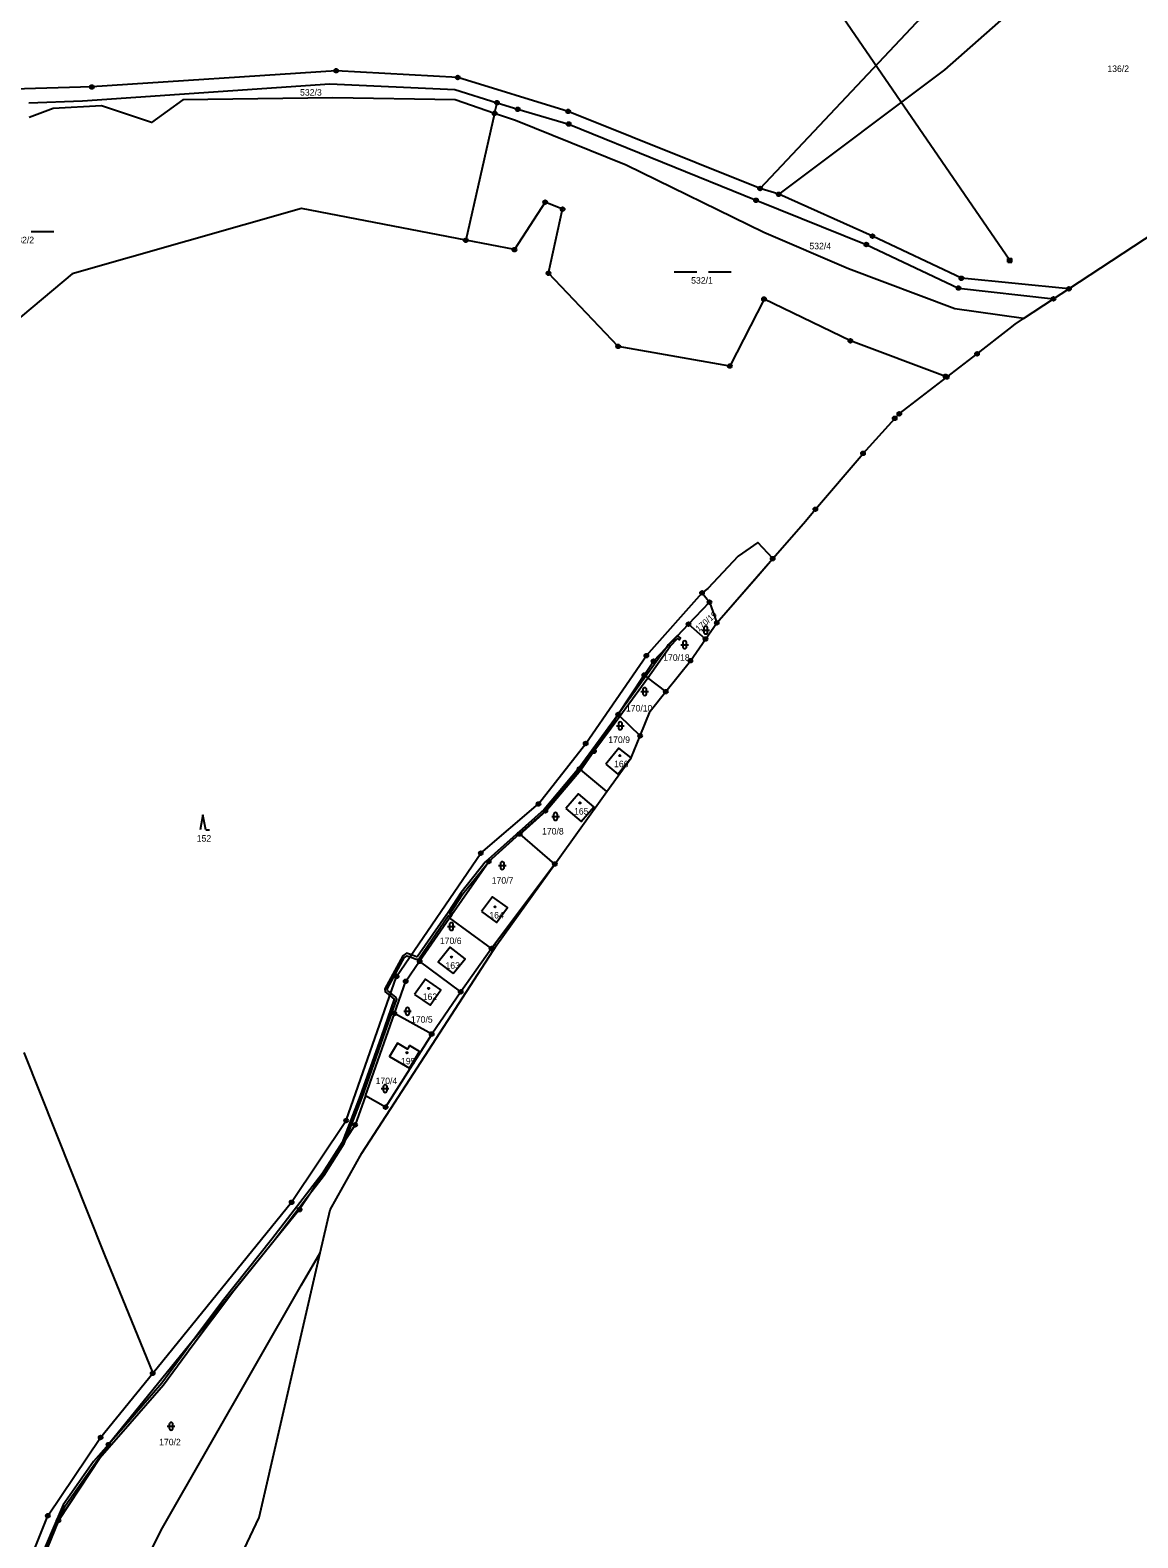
# Model space of a CAD drawing. Extents: x -758582 to -751794, y -998770 to -994350.
# Drawn here: x -755930.2 to -755639.5, y -996868.5 to -996472.9 of the extents above; entities that cross this region are included whole.
import ezdxf

# ---------------------------------------------------------------- set-up
doc = ezdxf.new("R2010")
doc.units = 0
for name, color, linetype in [('Hranice parcel', 7, 'Continuous'), ('Parcelní čísla', 7, 'Continuous'), ('Poz předměty', 7, 'Continuous'), ('Věcná břemena k části', 7, 'Continuous'), ('Značky bodu BP', 7, 'Continuous'), ('Značky budov', 7, 'Continuous'), ('Značky kultur', 7, 'Continuous')]:
    doc.layers.add(name, color=color, linetype=linetype)

msp = doc.modelspace()

# ---------------------------------------------------------------- linework, layer by layer
at = {"layer": 'Hranice parcel'}
for p, q in [((-755808.28, -996494.77), (-755807.65, -996491.97)), ((-755808.28, -996494.77), (-755815.82, -996528.07)), ((-755733.73, -996515.99), (-755738.63, -996514.47)), ((-755657.57, -996540.79), (-755632.12, -996524.1)), ((-755669.5, -996548.61), (-755661.64, -996543.45)), ((-755661.64, -996543.45), (-755657.57, -996540.79)), ((-755689.6, -996563.96), (-755681.68, -996557.85)), ((-755757.39, -996628.81), (-755751.89, -996623.03)), ((-755751.89, -996623.03), (-755749.99, -996628.46)), ((-755752.94, -996632.69), (-755757.39, -996628.81)), ((-755752.94, -996632.69), (-755749.99, -996628.46)), ((-755775.86, -996652.51), (-755769.01, -996642.14)), ((-755772.48, -996663.86), (-755770.1, -996658.08)), ((-755778.8, -996672.66), (-755772.48, -996663.86)), ((-755792.5, -996691.74), (-755778.8, -996672.66)), ((-755792.5, -996691.74), (-755809.1, -996713.88)), ((-755827.96, -996717.24), (-755820.08, -996705.87)), ((-755809.1, -996713.88), (-755820.08, -996705.87)), ((-755817.17, -996725.28), (-755827.96, -996717.24)), ((-755809.1, -996713.88), (-755817.17, -996725.28)), ((-755817.17, -996725.28), (-755824.8, -996736.35)), ((-755842.13, -996752.56), (-755834.58, -996730.95)), ((-755824.8, -996736.35), (-755834.58, -996730.95))]:
    msp.add_line(p, q, dxfattribs=at)
for points in [[(-755738.63, -996514.47), (-755697.58, -996470.89), (-755661.47, -996437.55), (-755587.13, -996400.84)], [(-755578.05, -996410.74), (-755604.07, -996420.95), (-755651.18, -996448.91), (-755690.24, -996483.38), (-755733.73, -996515.99)], [(-755738.63, -996514.47), (-755788.99, -996494.25), (-755817.97, -996485.34), (-755849.85, -996483.58), (-755913.99, -996487.85), (-755981.92, -996489.8), (-756037.02, -996471.24)], [(-755930.55, -996492.03), (-755916.39, -996491.48), (-755851.5, -996487.03), (-755818.69, -996488.48), (-755807.65, -996491.97)], [(-755808.28, -996494.77), (-755818.67, -996491.26), (-755850.72, -996490.71), (-755890.14, -996491.25), (-755898.35, -996497.16), (-755911.43, -996492.83), (-755924.16, -996493.48), (-755930.4, -996495.89)], [(-755807.65, -996491.97), (-755802.23, -996493.69), (-755788.84, -996497.56), (-755739.69, -996517.57), (-755710.74, -996529.16), (-755686.54, -996540.6), (-755661.64, -996543.45)], [(-755669.5, -996548.61), (-755687.54, -996546.02), (-755715.4, -996535.58), (-755737.6, -996526.05), (-755773.75, -996508.36), (-755802.77, -996496.64), (-755808.28, -996494.77)], [(-755657.57, -996540.79), (-755685.81, -996538.04), (-755709.11, -996527), (-755733.73, -996515.99)], [(-755815.82, -996528.07), (-755858.93, -996519.76), (-755919.17, -996536.86), (-755937.62, -996552.31), (-755950.67, -996566.72), (-755976.44, -996592.58), (-755981.16, -996620.43)], [(-755689.6, -996563.96), (-755689.98, -996563.77), (-755714.93, -996554.46), (-755737.59, -996543.48), (-755746.56, -996561.07), (-755775.86, -996555.9), (-755794.16, -996536.73), (-755790.43, -996519.91), (-755795.01, -996518.06), (-755803.05, -996530.53), (-755815.82, -996528.07)], [(-755681.68, -996557.85), (-755673.35, -996551.41), (-755671.71, -996550.06), (-755669.5, -996548.61)], [(-755724.11, -996598.64), (-755711.6, -996583.98), (-755703.29, -996574.79), (-755702.09, -996573.61), (-755689.6, -996563.96)], [(-755749.99, -996628.46), (-755735.31, -996611.6), (-755727.27, -996602.34), (-755724.11, -996598.64)], [(-755898.01, -996825.36), (-755861.55, -996780.48), (-755847.22, -996759.03), (-755834, -996721.24), (-755811.89, -996688.88), (-755796.75, -996675.97), (-755784.39, -996660.1), (-755768.45, -996637.05), (-755753.84, -996620.59), (-755751.89, -996623.03)], [(-755769.01, -996642.14), (-755766.6, -996638.49), (-755763.22, -996634.94), (-755760.28, -996631.84), (-755757.39, -996628.81)], [(-755763.36, -996646.5), (-755756.9, -996638.39), (-755752.94, -996632.69)], [(-755763.36, -996646.5), (-755768.1, -996642.84), (-755768.57, -996642.48), (-755769.01, -996642.14)], [(-755770.1, -996658.08), (-755767.47, -996651.66), (-755763.36, -996646.5)], [(-755785.99, -996666.78), (-755782.21, -996662.14), (-755780.54, -996659.61), (-755775.86, -996652.51)], [(-755770.1, -996658.08), (-755775.41, -996652.94), (-755775.86, -996652.51)], [(-755779.08, -996665.54), (-755775.96, -996668.12), (-755772.48, -996663.86), (-755775.67, -996661.32), (-755779.08, -996665.54)], [(-755801.71, -996683.83), (-755794.95, -996677.78), (-755785.99, -996666.78)], [(-755778.8, -996672.66), (-755785.7, -996667.01), (-755785.99, -996666.78)], [(-755789.63, -996677.2), (-755785.56, -996680.61), (-755782.23, -996676.69), (-755786.3, -996673.28), (-755789.63, -996677.2)], [(-755820.08, -996705.87), (-755809.82, -996691.08), (-755801.71, -996683.83)], [(-755792.5, -996691.74), (-755801.62, -996683.9), (-755801.71, -996683.83)], [(-755834.58, -996754.4), (-755807.73, -996712.95), (-755792.5, -996691.74)], [(-755811.71, -996704.23), (-755807.78, -996707.09), (-755804.88, -996703.16), (-755808.81, -996700.3), (-755811.71, -996704.23)], [(-755819.12, -996720.47), (-755816.03, -996716.57), (-755819.97, -996713.54), (-755823.06, -996717.44), (-755819.12, -996720.47)], [(-755834.58, -996730.95), (-755831.61, -996722.5), (-755827.96, -996717.24)], [(-755829.28, -996725.96), (-755825.21, -996728.78), (-755822.37, -996724.76), (-755826.44, -996721.94), (-755829.28, -996725.96)], [(-755824.8, -996736.35), (-755836.88, -996755.52), (-755842.13, -996752.56)], [(-755931.83, -996741.15), (-755910.72, -996794.08), (-755898.01, -996825.36)], [(-755830.58, -996739.32), (-755831.16, -996740.28), (-755833.76, -996738.71), (-755835.86, -996742.2), (-755830.61, -996745.26), (-755828.03, -996740.95), (-755830.58, -996739.32)], [(-755842.13, -996752.56), (-755844.87, -996760.17), (-755847.24, -996763.79), (-755856.29, -996777.57), (-755859.45, -996782.4), (-755876.73, -996803.64), (-755887.26, -996816.58), (-755909.61, -996844.06), (-755911.91, -996847.55), (-755922.74, -996863.98), (-755929.65, -996880.94)], [(-755854.08, -996793.78), (-755851.47, -996782.48), (-755843.14, -996767.6), (-755834.58, -996754.4)], [(-756022.26, -997113.5), (-756011.99, -997101.75), (-755985.49, -997047.21), (-755966.82, -997010.05), (-755936.62, -996949.43), (-755895.76, -996866.55), (-755859, -996802.15), (-755854.08, -996793.78)], [(-755898.17, -996922.45), (-755870.08, -996863.18), (-755854.08, -996793.78)], [(-755974.34, -996958.81), (-755964.78, -996942.7), (-755957.3, -996921.12), (-755942.83, -996899.6), (-755933.64, -996883.15), (-755925.53, -996862.72), (-755911.68, -996842.2), (-755898.01, -996825.36)]]:
    msp.add_lwpolyline(points, dxfattribs=at)
at = {"layer": 'Poz předměty'}
for p, q in [((-755728.44, -996452.68), (-755673.1, -996533.33)), ((-755673.6, -996532.83), (-755672.6, -996532.83)), ((-755673.6, -996533.83), (-755673.6, -996532.83)), ((-755673.6, -996533.03), (-755672.6, -996533.03)), ((-755673.6, -996533.23), (-755672.6, -996533.23)), ((-755673.6, -996533.43), (-755672.6, -996533.43)), ((-755673.6, -996533.63), (-755672.6, -996533.63)), ((-755673.6, -996533.83), (-755672.6, -996533.83)), ((-755673.4, -996533.83), (-755673.4, -996532.83)), ((-755673.2, -996533.83), (-755673.2, -996532.83)), ((-755673, -996533.83), (-755673, -996532.83)), ((-755672.8, -996533.83), (-755672.8, -996532.83)), ((-755672.6, -996533.83), (-755672.6, -996532.83))]:
    msp.add_line(p, q, dxfattribs=at)
at = {"layer": 'Věcná břemena k části'}
for points in [[(-755753.84, -996620.59), (-755751.89, -996623.03), (-755749.99, -996628.46), (-755739.78, -996616.73), (-755735.31, -996611.6), (-755739.22, -996607.41), (-755744.41, -996610.93), (-755752.35, -996619.41)], [(-755768.57, -996642.48), (-755768.1, -996642.84), (-755762.24, -996634.6), (-755760.27, -996632.59), (-755759.83, -996632.91), (-755759.48, -996632.42), (-755760.28, -996631.84), (-755763.22, -996634.94)], [(-755763.22, -996634.94), (-755760.28, -996631.84), (-755760.33, -996631.8), (-755762.7, -996634.21)], [(-755775.86, -996652.51), (-755775.41, -996652.94), (-755768.1, -996642.84), (-755768.57, -996642.48)], [(-755830.13, -996715.57), (-755830.48, -996716.09), (-755828.88, -996716.66), (-755828.2, -996716.57), (-755820.36, -996705.26), (-755819.89, -996705.6), (-755819.55, -996705.11), (-755820.02, -996704.76), (-755816.61, -996699.55), (-755810, -996691.33), (-755809.82, -996691.08), (-755801.71, -996683.83), (-755794.95, -996677.78), (-755785.99, -996666.78), (-755782.21, -996662.14), (-755780.54, -996659.61), (-755775.86, -996652.51), (-755786.06, -996666.5), (-755795.25, -996677.45), (-755810.78, -996691.23), (-755817.09, -996699.19), (-755820.5, -996704.41), (-755828.54, -996716.01), (-755828.82, -996716.04)], [(-755775.41, -996652.94), (-755775.86, -996652.51), (-755782.21, -996662.14)], [(-755785.7, -996667.01), (-755782.21, -996662.14), (-755785.99, -996666.78)], [(-755785.99, -996666.78), (-755794.95, -996677.78), (-755801.71, -996683.83), (-755801.62, -996683.9), (-755794.82, -996677.87), (-755785.7, -996667.01)], [(-755835.75, -996726.24), (-755835.54, -996725.64), (-755836.43, -996724.92), (-755836.49, -996724.58), (-755831.93, -996716.21), (-755831.3, -996715.79), (-755830.48, -996716.09), (-755830.13, -996715.57), (-755831.38, -996715.12), (-755832.39, -996715.79), (-755837.11, -996724.47), (-755836.99, -996725.23)], [(-755887.26, -996816.58), (-755876.73, -996803.64), (-755866.26, -996790.56), (-755856.29, -996777.57), (-755847.24, -996763.79), (-755842.97, -996752.73), (-755837.49, -996737.24), (-755833.97, -996727.15), (-755834.22, -996726.64), (-755835.54, -996725.64), (-755835.75, -996726.24), (-755834.62, -996727.19), (-755838.06, -996737.04), (-755843.54, -996752.52), (-755848.29, -996764.83), (-755853.54, -996773.02), (-755866.73, -996790.19), (-755879.73, -996806.43)], [(-755853.05, -996773.36), (-755847.75, -996765.1), (-755847.24, -996763.79), (-755856.29, -996777.57)], [(-755888.67, -996818.53), (-755889.54, -996819.68), (-755895.61, -996827.97), (-755904.42, -996838.15), (-755909.61, -996844.06), (-755911.91, -996847.55), (-755903.97, -996838.54), (-755895.15, -996828.35), (-755889.06, -996820.04), (-755888.19, -996818.89), (-755876.73, -996803.64), (-755887.26, -996816.58)]]:
    msp.add_lwpolyline(points, close=True, dxfattribs=at)
msp.add_lwpolyline([(-755927.96, -996876.5), (-755922.74, -996863.98), (-755921, -996860.15), (-755913.04, -996848.83), (-755909.61, -996844.06), (-755913.51, -996848.46), (-755921.52, -996859.86), (-755928.52, -996876.26)], dxfattribs=at)
at = {"layer": 'Značky bodu BP'}
for centre, radius in [((-755849.85, -996483.58), 0.5), ((-755849.85, -996483.58), 0.0303), ((-755913.99, -996487.85), 0.5), ((-755913.99, -996487.85), 0.0303), ((-755817.97, -996485.34), 0.5), ((-755817.97, -996485.34), 0.0303), ((-755807.65, -996491.97), 0.5), ((-755807.65, -996491.97), 0.0303), ((-755808.28, -996494.77), 0.5), ((-755808.28, -996494.77), 0.0303), ((-755802.23, -996493.69), 0.5), ((-755802.23, -996493.69), 0.0303), ((-755788.99, -996494.25), 0.5), ((-755788.99, -996494.25), 0.0303), ((-755788.84, -996497.56), 0.5), ((-755788.84, -996497.56), 0.0303), ((-755738.63, -996514.47), 0.5), ((-755738.63, -996514.47), 0.0303), ((-755733.73, -996515.99), 0.5), ((-755733.73, -996515.99), 0.0303), ((-755795.01, -996518.06), 0.5), ((-755795.01, -996518.06), 0.0303), ((-755790.43, -996519.91), 0.5), ((-755790.43, -996519.91), 0.0303), ((-755739.69, -996517.57), 0.5), ((-755739.69, -996517.57), 0.0303), ((-755815.82, -996528.07), 0.5), ((-755709.11, -996527), 0.5), ((-755709.11, -996527), 0.0303), ((-755815.82, -996528.07), 0.0303), ((-755803.05, -996530.53), 0.5), ((-755803.05, -996530.53), 0.0303), ((-755710.74, -996529.16), 0.5), ((-755710.74, -996529.16), 0.0303), ((-755794.16, -996536.73), 0.5), ((-755794.16, -996536.73), 0.0303), ((-755685.81, -996538.04), 0.5), ((-755685.81, -996538.04), 0.0303), ((-755737.59, -996543.48), 0.5), ((-755737.59, -996543.48), 0.0303), ((-755686.54, -996540.6), 0.5), ((-755686.54, -996540.6), 0.0303), ((-755661.64, -996543.45), 0.5), ((-755661.64, -996543.45), 0.0303), ((-755657.57, -996540.79), 0.5), ((-755657.57, -996540.79), 0.0303), ((-755775.86, -996555.9), 0.5), ((-755714.93, -996554.46), 0.5), ((-755714.93, -996554.46), 0.0303), ((-755775.86, -996555.9), 0.0303), ((-755681.68, -996557.85), 0.5), ((-755681.68, -996557.85), 0.0303), ((-755746.56, -996561.07), 0.5), ((-755746.56, -996561.07), 0.0303), ((-755689.98, -996563.77), 0.5), ((-755689.6, -996563.96), 0.5), ((-755689.98, -996563.77), 0.0303), ((-755689.6, -996563.96), 0.0303), ((-755703.29, -996574.79), 0.5), ((-755703.29, -996574.79), 0.0303), ((-755702.09, -996573.61), 0.5), ((-755702.09, -996573.61), 0.0303), ((-755711.6, -996583.98), 0.5), ((-755711.6, -996583.98), 0.0303), ((-755724.11, -996598.64), 0.5), ((-755724.11, -996598.64), 0.0303), ((-755735.31, -996611.6), 0.5), ((-755735.31, -996611.6), 0.0303), ((-755753.84, -996620.59), 0.5), ((-755753.84, -996620.59), 0.0303), ((-755751.89, -996623.03), 0.5), ((-755751.89, -996623.03), 0.0303), ((-755757.39, -996628.81), 0.5), ((-755757.39, -996628.81), 0.0303), ((-755749.99, -996628.46), 0.5), ((-755749.99, -996628.46), 0.0303), ((-755752.94, -996632.69), 0.5), ((-755752.94, -996632.69), 0.0303), ((-755768.45, -996637.05), 0.5), ((-755768.45, -996637.05), 0.0303), ((-755766.6, -996638.49), 0.5), ((-755766.6, -996638.49), 0.0303), ((-755756.9, -996638.39), 0.5), ((-755756.9, -996638.39), 0.0303), ((-755769.01, -996642.14), 0.5), ((-755769.01, -996642.14), 0.0303), ((-755763.36, -996646.5), 0.5), ((-755763.36, -996646.5), 0.0303), ((-755775.86, -996652.51), 0.5), ((-755775.86, -996652.51), 0.0303), ((-755770.1, -996658.08), 0.5), ((-755770.1, -996658.08), 0.0303), ((-755784.39, -996660.1), 0.5), ((-755784.39, -996660.1), 0.0303), ((-755782.21, -996662.14), 0.5), ((-755782.21, -996662.14), 0.0303), ((-755785.99, -996666.78), 0.5), ((-755785.99, -996666.78), 0.0303), ((-755796.75, -996675.97), 0.5), ((-755796.75, -996675.97), 0.0303), ((-755794.95, -996677.78), 0.5), ((-755794.95, -996677.78), 0.0303), ((-755801.71, -996683.83), 0.5), ((-755801.71, -996683.83), 0.0303), ((-755811.89, -996688.88), 0.5), ((-755811.89, -996688.88), 0.0303), ((-755809.82, -996691.08), 0.5), ((-755809.82, -996691.08), 0.0303), ((-755792.5, -996691.74), 0.5), ((-755792.5, -996691.74), 0.0303), ((-755809.1, -996713.88), 0.5), ((-755827.96, -996717.24), 0.5), ((-755827.96, -996717.24), 0.0303), ((-755809.1, -996713.88), 0.0303), ((-755834, -996721.24), 0.5), ((-755834, -996721.24), 0.0303), ((-755831.61, -996722.5), 0.5), ((-755831.61, -996722.5), 0.0303), ((-755817.17, -996725.28), 0.5), ((-755817.17, -996725.28), 0.0303), ((-755834.58, -996730.95), 0.5), ((-755834.58, -996730.95), 0.0303), ((-755824.8, -996736.35), 0.5), ((-755824.8, -996736.35), 0.0303), ((-755836.88, -996755.52), 0.5), ((-755836.88, -996755.52), 0.0303), ((-755847.22, -996759.03), 0.5), ((-755847.22, -996759.03), 0.0303), ((-755844.87, -996760.17), 0.5), ((-755844.87, -996760.17), 0.0303), ((-755861.55, -996780.48), 0.5), ((-755861.55, -996780.48), 0.0303), ((-755859.45, -996782.4), 0.5), ((-755859.45, -996782.4), 0.0303), ((-755898.01, -996825.36), 0.5), ((-755898.01, -996825.36), 0.0303), ((-755911.68, -996842.2), 0.5), ((-755911.68, -996842.2), 0.0303), ((-755909.61, -996844.06), 0.5), ((-755909.61, -996844.06), 0.0303), ((-755925.53, -996862.72), 0.5), ((-755925.53, -996862.72), 0.0303), ((-755922.74, -996863.98), 0.5), ((-755922.74, -996863.98), 0.0303)]:
    msp.add_circle(centre, radius, dxfattribs=at)
at = {"layer": 'Značky budov'}
for centre in [(-755775.43, -996663.27), (-755785.9, -996675.7), (-755808.17, -996702.96), (-755819.6, -996716.15), (-755825.59, -996724.35), (-755831.31, -996741.24)]:
    msp.add_circle(centre, 0.175, dxfattribs=at)
at = {"layer": 'Značky kultur'}
for p, q in [((-755929.93, -996525.8), (-755923.93, -996525.8)), ((-755761.2, -996536.39), (-755755.2, -996536.39)), ((-755752.2, -996536.39), (-755746.2, -996536.39)), ((-755753.88, -996630.35), (-755751.88, -996630.35)), ((-755753.38, -996629.85), (-755753.38, -996630.85)), ((-755752.38, -996630.85), (-755752.38, -996629.85)), ((-755759.41, -996634.19), (-755757.41, -996634.19)), ((-755758.91, -996633.69), (-755758.91, -996634.69)), ((-755757.91, -996634.69), (-755757.91, -996633.69)), ((-755769.9, -996646.49), (-755767.9, -996646.49)), ((-755769.4, -996645.99), (-755769.4, -996646.99)), ((-755768.4, -996646.99), (-755768.4, -996645.99)), ((-755776.3, -996655.46), (-755774.3, -996655.46)), ((-755775.8, -996654.96), (-755775.8, -996655.96)), ((-755774.8, -996655.96), (-755774.8, -996654.96)), ((-755884.83, -996678.8), (-755885.58, -996682.8)), ((-755884.08, -996682.8), (-755884.83, -996678.8)), ((-755793.3, -996679.25), (-755791.3, -996679.25)), ((-755792.8, -996678.75), (-755792.8, -996679.75)), ((-755791.8, -996679.75), (-755791.8, -996678.75)), ((-755884.08, -996682.8), (-755883.08, -996682.8)), ((-755807.28, -996692.14), (-755805.28, -996692.14)), ((-755806.78, -996691.64), (-755806.78, -996692.64)), ((-755805.78, -996692.64), (-755805.78, -996691.64)), ((-755820.62, -996708.12), (-755818.62, -996708.12)), ((-755820.12, -996707.62), (-755820.12, -996708.62)), ((-755819.12, -996708.62), (-755819.12, -996707.62)), ((-755832.14, -996730.38), (-755830.14, -996730.38)), ((-755831.64, -996729.88), (-755831.64, -996730.88)), ((-755830.64, -996730.88), (-755830.64, -996729.88)), ((-755838.02, -996750.66), (-755836.02, -996750.66)), ((-755837.52, -996750.16), (-755837.52, -996751.16)), ((-755836.52, -996751.16), (-755836.52, -996750.16)), ((-755894.18, -996839.25), (-755892.18, -996839.25)), ((-755893.68, -996838.75), (-755893.68, -996839.75)), ((-755892.68, -996839.75), (-755892.68, -996838.75))]:
    msp.add_line(p, q, dxfattribs=at)
for centre, start, end in [((-755752.88, -996629.85), 0, 180), ((-755758.41, -996633.69), 0, 180), ((-755758.41, -996634.69), 180, 359.9879), ((-755752.88, -996630.85), 180, 359.9879), ((-755768.9, -996645.99), 0, 180), ((-755768.9, -996646.99), 180, 359.9879), ((-755775.3, -996654.96), 0, 180), ((-755775.3, -996655.96), 180, 359.9879), ((-755792.3, -996678.75), 0, 180), ((-755792.3, -996679.75), 180, 359.9879), ((-755806.28, -996691.64), 0, 180), ((-755806.28, -996692.64), 180, 359.9879), ((-755819.62, -996707.62), 0, 180), ((-755819.62, -996708.62), 180, 359.9879), ((-755831.14, -996729.88), 0, 180), ((-755831.14, -996730.88), 180, 359.9879), ((-755837.02, -996750.16), 0, 180), ((-755837.02, -996751.16), 180, 359.9879), ((-755893.18, -996838.75), 0, 180), ((-755893.18, -996839.75), 180, 359.9879)]:
    msp.add_arc(centre, 0.5, start, end, dxfattribs=at)

# ---------------------------------------------------------------- texts
at = {"layer": 'Parcelní čísla'}
for s, p in [('136/2', (-755647.49, -996483.91)), ('532/3', (-755859.33, -996490.11)), ('532/2', (-755934.82, -996528.84)), ('532/4', (-755725.68, -996530.43)), ('532/1', (-755756.71, -996539.44)), ('170/18', (-755764.05, -996638.41)), ('170/10', (-755773.82, -996651.71)), ('170/9', (-755778.45, -996659.96)), ('166', (-755776.94, -996666.32)), ('165', (-755787.45, -996678.75)), ('152', (-755886.45, -996685.85)), ('170/8', (-755795.84, -996683.99)), ('170/7', (-755809.04, -996696.88)), ('164', (-755809.67, -996706.01)), ('170/6', (-755822.65, -996712.72)), ('163', (-755821.18, -996719.2)), ('162', (-755827.16, -996727.4)), ('170/5', (-755830.23, -996733.36)), ('195', (-755832.85, -996744.29)), ('170/4', (-755839.52, -996749.47)), ('170/2', (-755896.32, -996844.25))]:
    msp.add_text(s, height=1.7, dxfattribs=at).set_placement(p)
msp.add_text('170/19', height=1.606, rotation=41, dxfattribs=at).set_placement((-755754.72, -996630.83))

doc.saveas('drawing.dxf')
